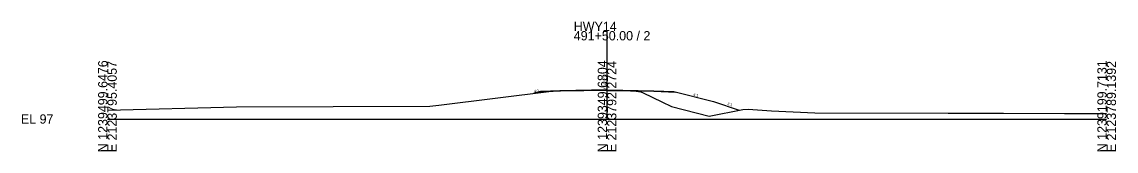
# Model space of a CAD drawing. Extents: x -26 to 303, y -10 to 11521.
# Drawn here: x -25.7 to 302.8, y 2990.3 to 3029.3 of the extents above; entities that cross this region are included whole.
import ezdxf

# ---------------------------------------------------------------- set-up
doc = ezdxf.new("R2010")
doc.units = 0
for name, color, linetype in [('XS_CELL', 7, 'Continuous'), ('XS_P_FINISHED_GRADE', 7, 'Continuous'), ('XS_P_SUBGRADE_GRANULAR', 7, 'Continuous'), ('XS_P_SUBGRADE_LEVELING', 7, 'Continuous'), ('XS_P_TX_FS_BS', 7, 'Continuous'), ('XS_X_GROUND', 7, 'Continuous'), ('XS_X_GROUND_TX', 7, 'Continuous')]:
    doc.layers.add(name, color=color, linetype=linetype)

msp = doc.modelspace()

# ---------------------------------------------------------------- linework, layer by layer
at = {"layer": 'XS_CELL'}
for p, q in [((150, 3000), (150, 3026.49)), ((0, 3000), (150, 3000)), ((150, 3000), (300, 3000))]:
    msp.add_line(p, q, dxfattribs=at)
at = {"layer": 'XS_P_FINISHED_GRADE'}
for p, q in [((130, 3008.25), (128.06, 3007.76)), ((136, 3008.49), (130, 3008.25)), ((150, 3008.77), (136, 3008.49)), ((150, 3008.77), (164, 3008.49)), ((164, 3008.49), (170, 3008.25)), ((170, 3008.25), (182, 3005.25)), ((182, 3005.25), (189.7, 3002.68))]:
    msp.add_line(p, q, dxfattribs=at)
at = {"layer": 'XS_P_SUBGRADE_GRANULAR'}
for p, q in [((136, 3008.36), (129.4, 3008.1)), ((164, 3008.36), (170.6, 3008.1))]:
    msp.add_line(p, q, dxfattribs=at)
at = {"layer": 'XS_P_SUBGRADE_LEVELING'}
for p, q in [((150, 3008.64), (136, 3008.36)), ((136, 3008.36), (136, 3008.49)), ((150, 3008.64), (164, 3008.36)), ((164, 3008.36), (164, 3008.49))]:
    msp.add_line(p, q, dxfattribs=at)
at = {"layer": 'XS_X_GROUND'}
for p, q in [((99.47, 3004.19), (133.33, 3008.42)), ((133.33, 3008.42), (135.78, 3008.58)), ((135.78, 3008.58), (145.32, 3008.8)), ((145.32, 3008.8), (146.59, 3008.83)), ((146.59, 3008.83), (148.52, 3008.79)), ((148.52, 3008.79), (150, 3008.77)), ((150, 3008.77), (157.24, 3008.63)), ((157.24, 3008.63), (160.17, 3008.21)), ((160.17, 3008.21), (160.8, 3007.91)), ((160.8, 3007.91), (166.41, 3005.21)), ((0, 3002.68), (38.78, 3003.68)), ((38.78, 3003.68), (96.76, 3003.85)), ((96.76, 3003.85), (99.47, 3004.19)), ((166.41, 3005.21), (169.35, 3003.76)), ((169.35, 3003.76), (180.63, 3000.84)), ((180.63, 3000.84), (190.74, 3002.89)), ((190.74, 3002.89), (192.33, 3002.96)), ((192.33, 3002.96), (199.41, 3002.5)), ((199.41, 3002.5), (212.35, 3001.84)), ((212.35, 3001.84), (252.46, 3001.75)), ((252.46, 3001.75), (269.03, 3001.72)), ((269.03, 3001.72), (287.36, 3001.67)), ((287.36, 3001.67), (300, 3001.65))]:
    msp.add_line(p, q, dxfattribs=at)

# ---------------------------------------------------------------- texts
at = {"layer": 'XS_CELL'}
for s, p in [('HWY14', (140, 3026.49)), ('491+50.00 / 2', (140, 3023.69)), ('EL 97', (-26, 2998.6))]:
    msp.add_text(s, height=2.8, dxfattribs=at).set_placement(p)
for s, p in [('N 1239499.6476', (0, 2990)), ('E 2123795.4057', (2.8, 2990)), ('N 1239349.6804', (150, 2990)), ('E 2123792.2724', (152.8, 2990)), ('N 1239199.7131', (300, 2990)), ('E 2123789.1392', (302.8, 2990))]:
    msp.add_text(s, height=2.8, rotation=90, dxfattribs=at).set_placement(p)
at = {"layer": 'XS_P_TX_FS_BS'}
for s, rotation, p in [('4:1', 14.0362, (128.2, 3007.92)), ('4:1', 345.9638, (175.82, 3007.03)), ('3:1', 341.5651, (186.02, 3004.28))]:
    msp.add_text(s, height=0.8, rotation=rotation, dxfattribs=at).set_placement(p)
at = {"layer": 'XS_X_GROUND_TX'}
msp.add_text('105.77', height=1, rotation=90, dxfattribs=at).set_placement((150, 3008.87))

doc.saveas('drawing.dxf')
